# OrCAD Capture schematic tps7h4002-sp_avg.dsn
size B; title: TPS7H4002-SP Radiation-Hardness-Assured 3-V to 5.5-V; rev: *; note: Datasheet: SLVSFL2    EVM User Guide: SLVUBI1; note: 3-A Synchronous Step-Down Converter
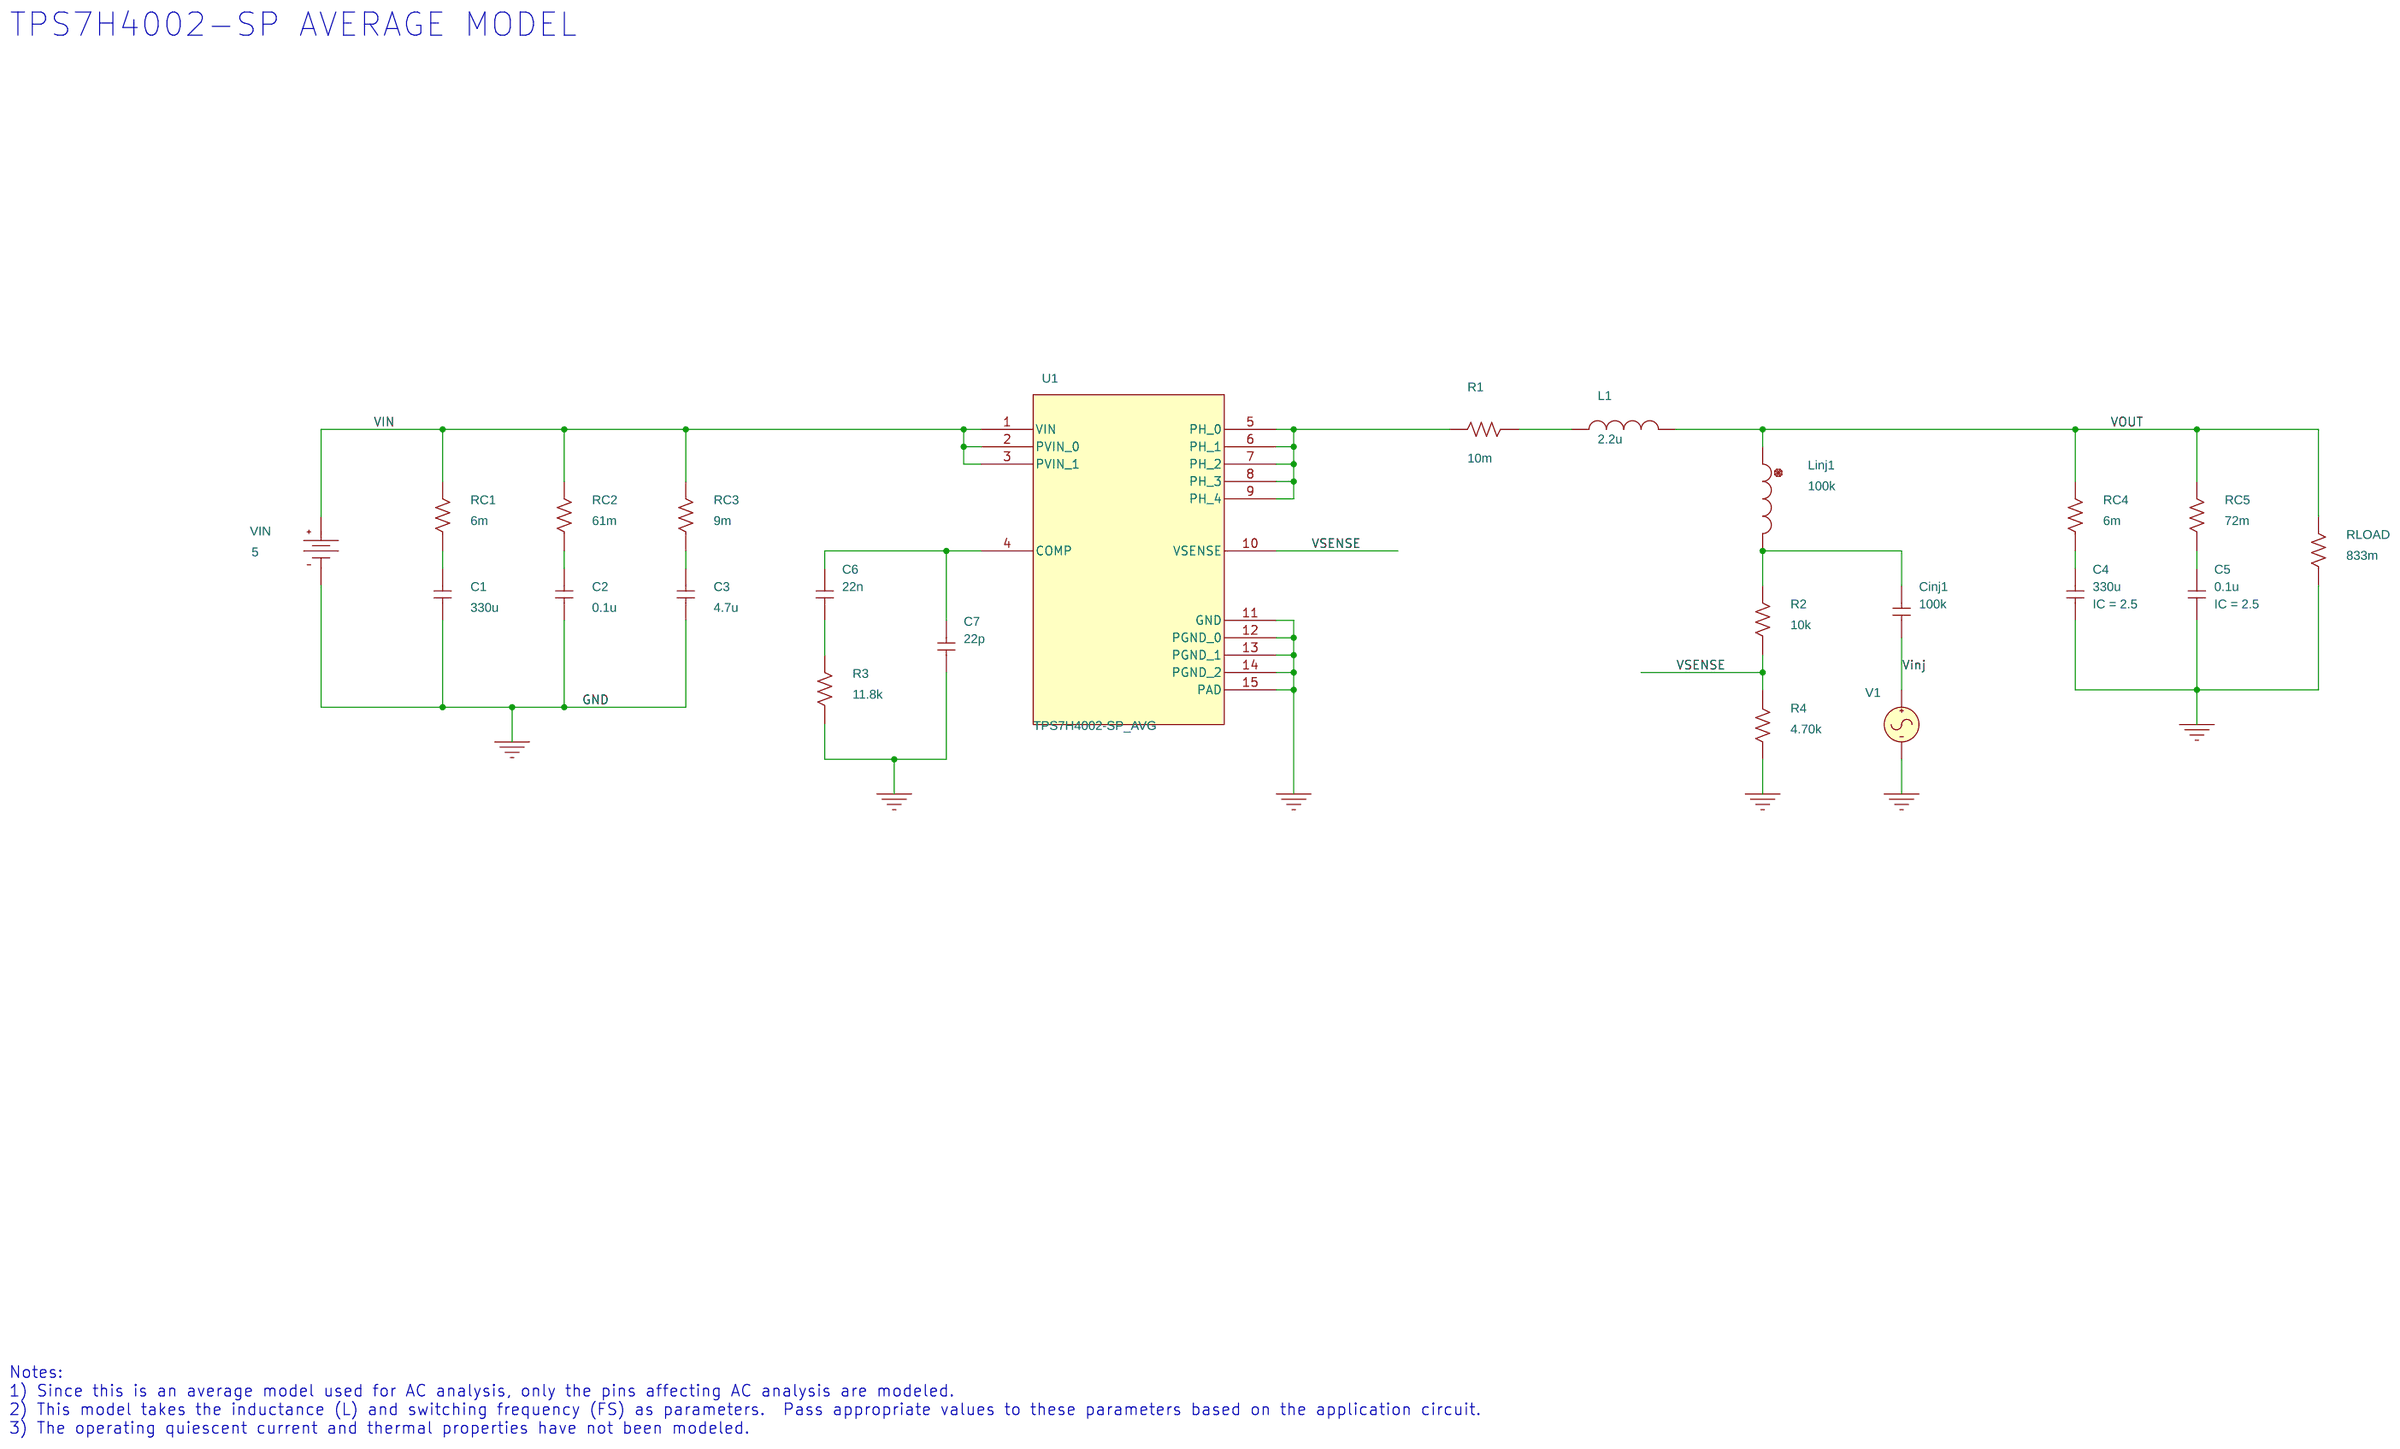
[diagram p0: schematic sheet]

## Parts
C1  330u  [RAD/CK05]
C2  0.1u  [RAD/CK05]
C3  4.7u  [RAD/CK05]
C4  330u  [RAD/CK05]
C5  0.1u  [RAD/CK05]
C6  22n  [RAD/CK05]
C7  22p  [RAD/CK05]
Cinj1  100k  [RAD/CK05]
L1  2.2u  [DISC/.350x.175/LS.200x.100/.034]
Linj1  100k  [DISC/.350x.175/LS.200x.100/.034]
R1  10m  [AX/RC05]
R2  10k  [AX/RC05]
R3  11.8k  [AX/RC05]
R4  4.70k  [AX/RC05]
RC1  6m  [AX/RC05]
RC2  61m  [AX/RC05]
RC3  9m  [AX/RC05]
RC4  6m  [AX/RC05]
RC5  72m  [AX/RC05]
RLOAD  833m  [AX/RC05]
U1  TPS7H4002-SP_AVG
V1  VAC
VIN  VDC

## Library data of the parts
C1-C3 C6 C7 Cinj1 = C
C4 C5 = C: IC: 2.5
L1 = L_v2
Linj1 = L
R1-R4 RC1-RC5 RLOAD = R
U1 = TPS7H4002-SP_AVG_1
V1 = VAC
VIN = VDC: DC: 5

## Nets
VIN: RC1.2 RC2.2 RC3.2 U1.1(VIN) U1.2(PVIN_0) U1.3(PVIN_1) VIN.0(+)
Vinj: Cinj1.2 V1.1(+)
0: C1.2 C2.2 C3.2 C4.2 C5.2 C7.2 R3.1 R4.2 RLOAD.1 U1.11(GND) U1.12(PGND_0) U1.13(PGND_1) U1.14(PGND_2) U1.15(PAD) V1.2(-) VIN.1(-)
VOUT: L1.2 Linj1.1 RC4.2 RC5.2 RLOAD.2
VSENSE: R2.1 R4.1 U1.10(VSENSE)
N16742446: C1.1 RC1.1
N16742450: C2.1 RC2.1
N16742456: C3.1 RC3.1
N16774042: L1.1 R1.1
N16774168: C4.1 RC4.1
N16774174: C5.1 RC5.1
N16774582: R1.2 U1.5(PH_0) U1.6(PH_1) U1.7(PH_2) U1.8(PH_3) U1.9(PH_4)
N16774816: C6.2 R3.2
N16774850: C6.1 C7.1 U1.4(COMP)
N16777182: Cinj1.1 Linj1.2 R2.2

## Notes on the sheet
- TPS7H4002-SP AVERAGE MODEL
- Notes:
  1) Since this is an average model used for AC analysis, only the pins affecting AC analysis are modeled.
  2) This model takes the inductance (L) and switching frequency (FS) as parameters.  Pass appropriate values to these parameters based on the application circuit.
  3) The operating quiescent current and thermal properties have not been modeled.
